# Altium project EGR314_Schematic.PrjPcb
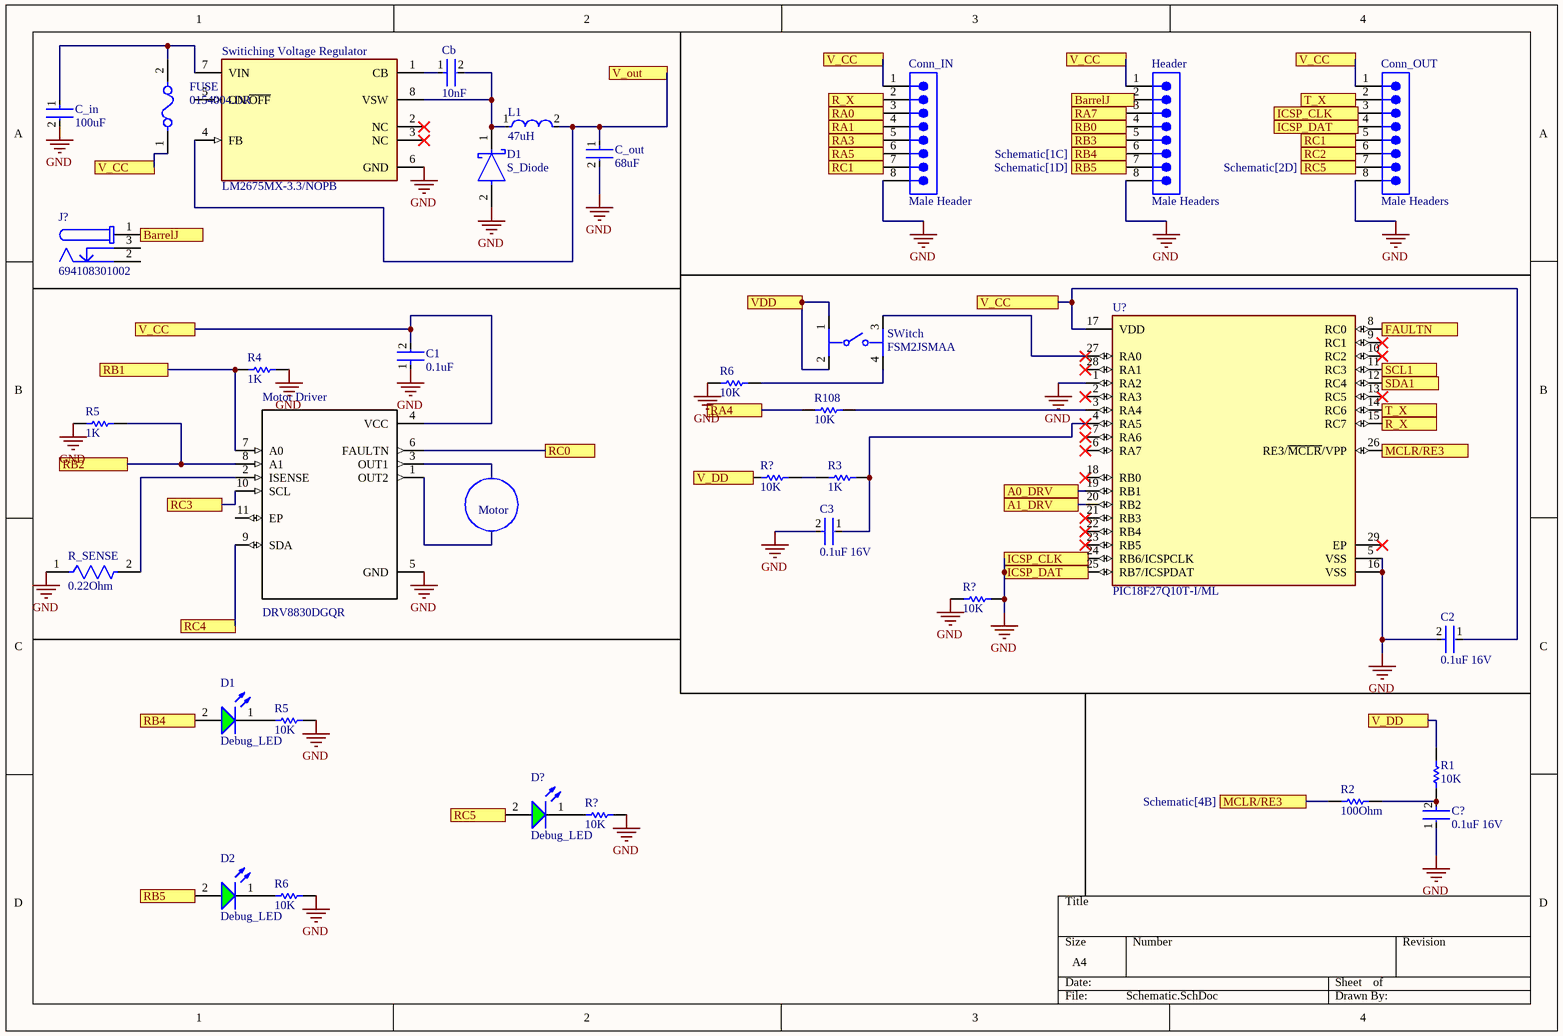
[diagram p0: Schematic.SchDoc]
1 sheet, 34 parts. Net scope: flat (ports and power ports of the same name join across sheets).

## Sheet Schematic.SchDoc
size A4; SheetNumber: 1; SheetTotal: 1

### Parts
(Parts that share a designator on the sheet are numbered #1, #2 ... from top to bottom, then left to right.)
C1  0.1uF  [FP-GRM033-0_03-MFG]
C2  0.1uF 16V  [FP-GRM15-MFG]
C3  0.1uF 16V  [FP-GRM15-MFG]
C?  0.1uF 16V  [FP-GRM15-MFG]
C_in  100uF  [FP-GRM32-0_3-MFG]
C_out  68uF  [FP-C5750-230-0_4-IPC_C]
Cb  10nF  [FP-GRM155-0_05-IPC_C]
Conn_IN  Male Header  [61300811121]
Conn_OUT  Male Headers  [61300811121]
D1#1  S_Diode  [FP-SMA-MFG]
D1#2  Debug_LED  [WL-SMCW_0603_150060xx75000]
D2  Debug_LED  [WL-SMCW_0603_150060xx75000]
D?  Debug_LED  [WL-SMCW_0603_150060xx75000]
FUSE  0154004.DR  [FP-0154-MFG]
Header  Male Headers  [61300811121]
J?  694108301002  [694108301002]
L1  47uH  [FP-IHLP-4040DZ-FP_3_124x3-MFG]
Motor_Driver  DRV8830DGQR  [*IC_XTR111AIDGQR]
R1  10K  [RESC1005X40X25LL05T05]
R2  100Ohm  [RESC1005X40X25LL05T05]
R3  1K  [RESC1608X55X30LL15T15]
R4  1K  [RESC1608X55X30LL15T15]
R5#1  1K  [RESC1608X55X30LL15T15]
R5#2  10K  [RESC1005X40X25LL05T05]
R6#1  10K  [RESC1005X40X25LL05T05]
R6#2  10K  [RESC1005X40X25LL05T05]
R108  10K  [RESC1005X40X25LL05T05]
R?#1  10K  [RESC1005X40X25LL05T05]
R?#2  10K  [RESC1005X40X25LL05T05]
R?#3  10K  [RESC1005X40X25LL05T05]
R_SENSE  0.22Ohm  [FP-ERJ1TR-MFG]
SWitch  FSM2JSMAA  [FP-FSM2JSMAA-MFG]
Switiching_Voltage_Regulator  LM2675MX-3.3/NOPB  [FP-D0008A-IPC_B]
U?  PIC18F27Q10T-I/ML  [FP-C04-105-MFG]

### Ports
A0_DRV, A1_DRV, BarrelJ (see Schematic[1A]), BarrelJ (see Schematic[3A]), FAULTN, ICSP_CLK (see Schematic[3C]), ICSP_CLK (see Schematic[4A]), ICSP_DAT (see Schematic[3C]), ICSP_DAT (see Schematic[4A]), MCLR/RE3 (see Schematic[4B]), MCLR/RE3 (see Schematic[4D]), R_X (see Schematic[3A]), R_X (see Schematic[4B]), RA0, RA1, RA3, RA4, RA5, RA7, RB0, RB1, RB2, RB3, RB4 (see Schematic[1C]), RB4 (see Schematic[3A]), RB5 (see Schematic[1D]), RB5 (see Schematic[3A]), RC0, RC1 (see Schematic[3A]), RC1 (see Schematic[4A]), RC2, RC3, RC4, RC5 (see Schematic[2D]), RC5 (see Schematic[4A]), SCL1, SDA1, T_X (see Schematic[4A]), T_X (see Schematic[4B]), V_CC (see Schematic[1A], Schematic[1B], Schematic[3A], Schematic[3B]), V_CC (see Schematic[1A], Schematic[1B], Schematic[3A], Schematic[3B], Schematic[4A]), V_CC (see Schematic[1A], Schematic[1B], Schematic[3A], Schematic[4A]), V_CC (see Schematic[1A], Schematic[3A], Schematic[3B], Schematic[4A]), V_CC (see Schematic[1B], Schematic[3A], Schematic[3B], Schematic[4A]), V_DD (see Schematic[2B]), V_DD (see Schematic[4C]), V_out, VDD

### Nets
GND: C1.1 C2.2 C3.2 C?.1 C_in.2 C_out.2 Conn_IN.8 Conn_OUT.8 D1#1.2(A) Header.8 Motor_Driver.5(GND) R4.2 R5#1.1 R5#2.2 R6#1.1 R6#2.2 R?#2.1 R?#2.2 R?#3.2 R_SENSE.1 Switiching_Voltage_Regulator.6(GND) U?.1(RA2) U?.5(VSS) U?.16(VSS) ; port ICSP_CLK, port ICSP_DAT
NetC1_2: C1.2 C2.1 Conn_IN.1 Conn_OUT.1 FUSE.1 Header.1 Motor_Driver.4(VCC) U?.17(VDD) ; port V_CC
NetC3_1: C3.1 R3.2 U?.4(RA5)
NetC?_2: C?.2 R1.1 R2.2
NetC_in_1: C_in.1 FUSE.2 Switiching_Voltage_Regulator.7(VIN)
NetC_out_1: C_out.1 L1.2 Switiching_Voltage_Regulator.4(FB) ; port V_out
NetCb_1: Cb.1 Switiching_Voltage_Regulator.1(CB)
NetCb_2: Cb.2 D1#1.1(C) L1.1 Switiching_Voltage_Regulator.8(VSW)
NetConn_IN_2: Conn_IN.2 U?.15(RC7) ; port R_X
NetConn_IN_3: Conn_IN.3 ; port RA0
NetConn_IN_4: Conn_IN.4 ; port RA1
NetConn_IN_5: Conn_IN.5 ; port RA3
NetConn_IN_6: Conn_IN.6 ; port RA5
NetConn_IN_7: Conn_IN.7 Conn_OUT.5 ; port RC1
NetConn_OUT_2: Conn_OUT.2 U?.14(RC6) ; port T_X
NetConn_OUT_6: Conn_OUT.6 ; port RC2
NetConn_OUT_7: Conn_OUT.7 D?.2(A) ; port RC5
NetD1#2_1: D1#2.1(K) R5#2.1
NetD1#2_2: D1#2.2(A) Header.6 ; port RB4
NetD2_1: D2.1(K) R6#2.1
NetD2_2: D2.2(A) Header.7 ; port RB5
NetD?_1: D?.1(K) R?#3.1
NetHeader_3: Header.3 ; port RA7
NetHeader_4: Header.4 ; port RB0
NetHeader_5: Header.5 ; port RB3
NetJ?_1: J?.1 ; port BarrelJ
NetMotor_Driver_2: Motor_Driver.2(ISENSE) R_SENSE.2
NetMotor_Driver_6: Motor_Driver.6(FAULTN) ; port RC0
NetMotor_Driver_7: Motor_Driver.7(A0) R4.1 ; port RB1
NetMotor_Driver_8: Motor_Driver.8(A1) R5#1.2 ; port RB2
NetMotor_Driver_9: Motor_Driver.9(SDA) ; port RC4
NetMotor_Driver_10: Motor_Driver.10(SCL) ; port RC3
NetR1_2: R1.2 ; port V_DD
NetR2_1: R2.1 U?.26(RE3/~{MCLR}/VPP) ; port MCLR/RE3
NetR3_1: R3.1 R?#1.2
NetR6#1_2: R6#1.2 SWitch.4
NetR108_1: R108.1 ; port RA4
NetR108_2: R108.2 U?.3(RA4)
NetSWitch_1: SWitch.1 SWitch.2 ; port VDD
NetSWitch_3: SWitch.3 U?.27(RA0)
NetU?_8: U?.8(RC0) ; port FAULTN
NetU?_11: U?.11(RC3) ; port SCL1
NetU?_12: U?.12(RC4) ; port SDA1
NetU?_19: U?.19(RB1) ; port A0_DRV
NetU?_20: U?.20(RB2) ; port A1_DRV

Not connected (* = marked no-connect by the designer): Conn_OUT 3 4; Header 2; J? 2 3; Motor_Driver 1(OUT2) 3(OUT1) 11(EP); R?#1 1; Switiching_Voltage_Regulator 2(NC)* 3(NC)* 5(ON/~{OFF}); U? 2(RA3)* 6(RA7)* 7(RA6)* 9(RC1)* 10(RC2)* 13(RC5)* 18(RB0)* 21(RB3)* 22(RB4)* 23(RB5)* 24(RB6/ICSPCLK) 25(RB7/ICSPDAT) 28(RA1)* 29(EP)*

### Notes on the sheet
- Motor

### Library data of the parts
C1 = CMP-06035-000062-2: Chip Multilayer Ceramic Capacitors for General Purpose, 0201, 0.10uF, X5R, 15%, 10%, 6.3V; Capacitance: 100nF
C2 C3 C? = CMP-2100-03641-2: CAP CER 0.1UF 16V X7R 0402; Manufacturer Part Number: GRM155R71C104KA88D; Manufacturer: Murata; Standoff Height: 0mm; Tolerance: 10%; Description: CAP Ceramic 0.10μF 10% X7R 16Vdc 0402 SMD; Voltage Rating: 16Vdc; Material: Ceramic; Capacitance: 0.10μF; Value: 0.10μF
C_in = CMP-2000-05259-2: CAP CER 100UF 6.3V X5R 1210; 3DS Part Number: 220-00002; Manufacturer Part Number: GRM32ER60J107ME20L; Manufacturer: Murata; Description: Chip Multilayer Ceramic Capacitors for General; Temperature Coefficient: 15%; Tolerance: 20%
C_out = CMP-08246-004950-1: Multilayer Ceramic Capacitors 68uF ±20% 10V X5R SMD 2220
Cb = CMP-2008-04637-5: Chip Multilayer Ceramic Capacitors for General Purpose, 0402, 10000pF, X7R, 15%, 10%, 50V; Voltage: 25V
Conn_IN Conn_OUT Header = CMP-1502-01076-3: NexarPartId: 32855533; Connector Type: Male Pin; Number of Contacts: 8; Voltage Rating: 250V; Current Rating: 3A; Contact Resistance: 20mΩ; Pitch: 2.54mm
D1#1 = CMP-12790-000051-1: DIODE SCHOTTKY 20V 1A SMA; Manufacturer: Diodes Inc.; Manufacturer Part Number: B120-13-F; Description: Diode Schottky 20V 1A Surface Mount SMA; Value: 110pF; Standoff Height: 0.05mm; Max Junction Temp: +150°C; Max Surge Forward Current: 30A; Peak Reverse Current: 0.5mA
D1#2 D2 D? = CMP-1426-00006-7: WURTH ELEKTRONIK - 150060VS75000 - LED, Green, SMD, 0603, 30 mA, 2 V, 570 nm; Reverse Voltage: 5V; Power Dissipation: 72mW; Dominant Wavelength: 570nm; Peak Wavelength: 572nm; Forward Current: 100mA; Forward Voltage: 2V; Lens Style: Clear, Rectangular; Test Current: 20mA; Max Junction Temperature (Tj): 95°C; Viewing Angle: 140°; Luminous Intensity: 40mcd
FUSE = CMP-08605-000003-1: FUSE BRD MNT 4A 125VAC/VDC 2SMD; Manufacturer: Littelfuse; Fuse Blow Speed: Fast; Max Fuse Ac Voltage: 125V
J? = CMP-1502-00190-3: NexarPartId: 52676102; Gender: Male; Voltage Rating: 24V; Insulation Resistance: 100MΩ; Voltage Rating (DC): 20V; Shielding: Unshielded; Connector Type: Power; Current Rating: 5A; Number of Contacts: 3
L1 = CMP-02424-000224-1: Commercial Inductors, Low DCR Series 47uH 3.3A 145mΩ 20%; Core Material: Metal; Saturation Current: 3A; Self Resonant Frequency: 1MHz; Test Frequency: 100kHz; Shielding: Shielded; DC Resistance (DCR): 145mR
Motor_Driver = DRV8830DGQR: 7-V, 1-A H-bridge motor driver with speed regulation and I2C control; MF: Texas Instruments
R1 R5#2 R6#1 R6#2 R108 R?#1-R?#3 = CMP-2000-07588-1: Chip Resistor, 10 KOhm, +/- 1%, 0.1 W, -55 to 155 degC, 0402 (1005 Metric), RoHS, Tape and Reel; Manufacturer: Panasonic; Power Rating: 100mW; Voltage Rating: 50V; Resistance: 10KOhm; Case\/Package: 0402; Temperature Coefficient: 100ppm\/degreesC
R2 = CMP-2002-00605-3: Chip Resistor, 100 Ohm, +/- 1%, 100 mW, -55 to 155 degC, 0402 (1005 Metric), RoHS, Tape and Reel; Manufacturer: Basic Passives; PartNumber: ERJ-2RKF1000X; Power Rating: 100 mW; Voltage Rating: 50 V; Case\/Package: 0402
R3 R4 R5#1 = CMP-2000-00180-1: Part Number: ERJ-3EKF1001V; Manufacturer: Panasonic
R_SENSE = CMP-05422-000060-1: RES 0.22 OHM 1% 1W 2512; Manufacturer: Panasonic; 3DS Part Number: 110-00006; Manufacturer Part Number: ERJ-1TRQFR22U; Description: PANASONIC ELECTRONIC COMPONENTS ERJ1TRQFR22U SMD Current Sense Resistor, 0.22 ohm, 2512 [6432 Metric], 1 W, 1%, ERJ1T Series; Value: 0.22Ω; Automotive Grade: Grade 0; Temperature Coefficient: 200ppm/°C
SWitch = CMP-03402-000003-1: SWITCH TACTILE SPST-NO 0.05A 24V; Manufacturer: TE Connectivity; Standoff Height: 0.05mm; Contact Current Rating: 50mA; Electromechanical Life: 100000Cycles; Operating Force: 260gf; Contact Resistance: 100mΩ
Switiching_Voltage_Regulator = CMP-04918-000266-1: IC REG BUCK 3.3V 1A 8SOIC; Efficiency: 86%; Switching Frequency: 260kHz; Quiescent Current: 2.5mA; Synchronous Rectifier: No; Max Input Voltage: 40V; Number of Outputs: 1; Min Input Voltage: 8V; Output Type: Fixed
U? = CMP-00252-96705243-1: PIC18F27Q10T-I/ML 8-bit PIC MCU, 128 KB, 3615 Bytes, 64 MHz, 1.8 to 5.5V, QFN-28, RoHS; Number of Timers/Counters: 4; Number of UART Channels: 2; Frequency: 64MHz; Number of I/Os: 25; Data Bus Width: 8b; Number of ADC Channels: 24; Min Supply Voltage: 1.8V; Number of A/D Converters: 1; Max Junction Temperature (Tj): 150°C; RAM Size: 3.5kB; Memory Type: FLASH; Memory Size: 128kB; Interface: I2C, LIN, SMBus, SPI, USART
